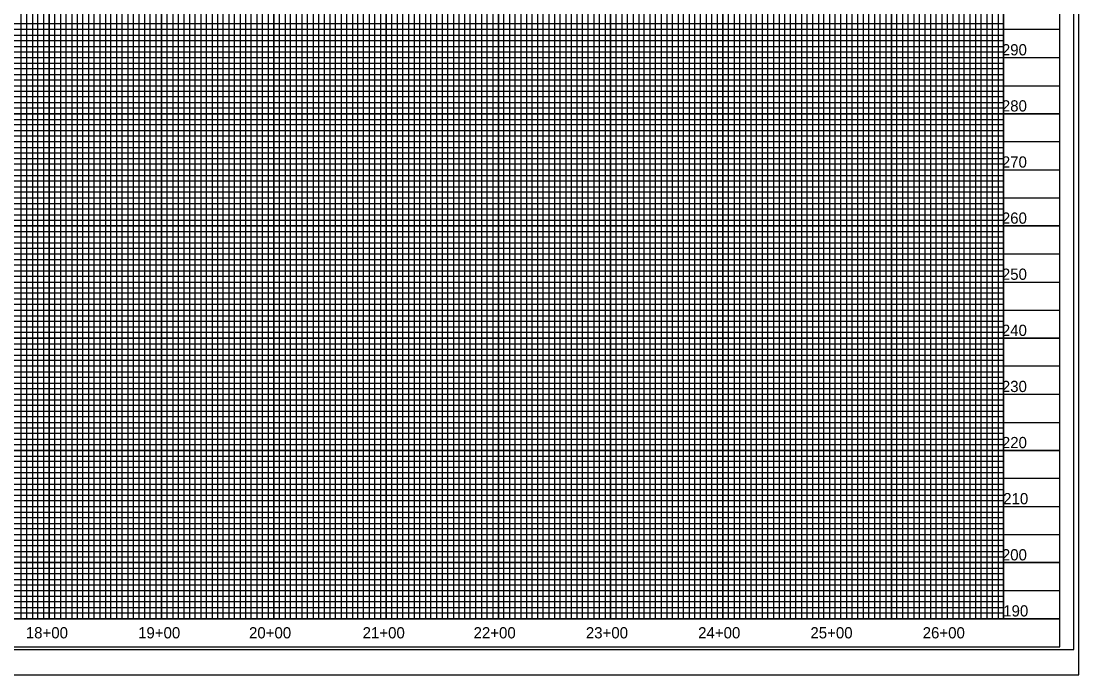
# Model space of a CAD drawing. Extents: x 10033 to 11717, y 9950 to 11050.
# Drawn here: x 10775 to 11717, y 9950 to 10532 of the extents above; entities that cross this region are included whole.
import ezdxf

# ---------------------------------------------------------------- set-up
doc = ezdxf.new("R2010")
doc.units = 0
for name, color, linetype in [('Exist Vertical Profile Horizontal Axis Label Major', 7, 'Continuous'), ('Exist Vertical Profile Vertical Axis Label', 7, 'Continuous'), ('Sheet Cutting Line CELL', 7, 'Continuous'), ('Sheet DOT Grid CELL', 7, 'Continuous'), ('Sheet Layout Profile Border', 7, 'Continuous'), ('Sheet Plot Border Inside CELL', 7, 'Continuous'), ('Sheet Plot Border Outside CELL', 7, 'Continuous'), ('Sheet Profile CELL', 7, 'Continuous'), ('Sheet Profile Grid Major CELL', 7, 'Continuous'), ('Sheet Profile Grid Middle CELL', 7, 'Continuous'), ('Sheet Profile Grid Minor CELL', 7, 'Continuous')]:
    doc.layers.add(name, color=color, linetype=linetype)

msp = doc.modelspace()

# ---------------------------------------------------------------- linework, layer by layer
at = {"layer": 'Sheet Cutting Line CELL'}
msp.add_line((10033, 9950), (11717, 9950), dxfattribs=at)
at = {"layer": 'Sheet DOT Grid CELL'}
for p, q in [((10800, 11025), (10800, 10000)), ((10850, 11025), (10850, 10000)), ((10900, 11025), (10900, 10000)), ((10950, 11025), (10950, 10000)), ((11000, 11025), (11000, 10000)), ((11050, 11025), (11050, 10000)), ((11100, 11025), (11100, 10000)), ((11150, 11025), (11150, 10000)), ((11200, 11025), (11200, 10000)), ((11250, 11025), (11250, 10000)), ((11300, 11025), (11300, 10000)), ((11350, 11025), (11350, 10000)), ((11400, 11025), (11400, 10000)), ((11450, 11025), (11450, 10000)), ((11500, 10000), (11500, 10887.45)), ((11550, 10000), (11550, 10887.45)), ((11600, 10000), (11600, 10887.45)), ((11650, 10000), (11650, 10887.45)), ((10200, 10500), (11700, 10500)), ((10200, 10450), (11700, 10450)), ((10200, 10400), (11700, 10400)), ((10200, 10350), (11700, 10350)), ((10200, 10300), (11700, 10300)), ((10200, 10250), (11700, 10250)), ((10200, 10200), (11700, 10200)), ((10200, 10150), (11700, 10150)), ((10200, 10100), (11700, 10100)), ((10200, 10050), (11700, 10050))]:
    msp.add_line(p, q, dxfattribs=at)
at = {"layer": 'Sheet Layout Profile Border'}
msp.add_lwpolyline([(10250, 11025), (10250, 10000), (11650, 10000), (11650, 10887.45), (11499.95, 10887.45), (11499.95, 11025)], close=True, dxfattribs=at)
at = {"layer": 'Sheet Plot Border Inside CELL'}
msp.add_lwpolyline([(11712.5, 11027.55), (10046, 11027.55), (10046, 9972.45), (11712.5, 9972.45)], close=True, dxfattribs=at)
at = {"layer": 'Sheet Plot Border Outside CELL'}
msp.add_lwpolyline([(11717, 11050), (10033, 11050), (10033, 9950), (11717, 9950)], close=True, dxfattribs=at)
at = {"layer": 'Sheet Profile CELL'}
msp.add_line((11700, 10000), (10200, 10000), dxfattribs=at)
msp.add_lwpolyline([(11700, 11025), (10200, 11025), (10200, 9975), (11700, 9975)], close=True, dxfattribs=at)
at = {"layer": 'Sheet Profile Grid Major CELL'}
for points in [[(10750, 10000), (10800, 10000), (10800, 11025)], [(10850, 11025), (10850, 10000), (10900, 10000), (10900, 11025)], [(10950, 11025), (10950, 10000), (11000, 10000), (11000, 11025)], [(11050, 11025), (11050, 10000), (11100, 10000), (11100, 11025)], [(11150, 11025), (11150, 10000), (11200, 10000), (11200, 11025)], [(11250, 11025), (11250, 10000), (11300, 10000), (11300, 11025)], [(11350, 11025), (11350, 10000), (11400, 10000), (11400, 11025)], [(11450, 11025), (11450, 10000), (11500, 10000), (11500, 11025)], [(11550, 10887.45), (11550, 10000), (11600, 10000), (11600, 10887.45)], [(11650, 10887.45), (11650, 10000), (11700, 10000)], [(11700, 10450), (10200, 10450), (10200, 10500), (11700, 10500)], [(11700, 10350), (10200, 10350), (10200, 10400), (11700, 10400)], [(11700, 10250), (10200, 10250), (10200, 10300), (11700, 10300)], [(11700, 10150), (10200, 10150), (10200, 10200), (11700, 10200)], [(11700, 10050), (10200, 10050), (10200, 10100), (11700, 10100)]]:
    msp.add_lwpolyline(points, dxfattribs=at)
at = {"layer": 'Sheet Profile Grid Middle CELL'}
for points in [[(10725, 10000), (10775, 10000), (10775, 11025)], [(10825, 11025), (10825, 10000), (10875, 10000), (10875, 11025)], [(10925, 11025), (10925, 10000), (10975, 10000), (10975, 11025)], [(11025, 11025), (11025, 10000), (11075, 10000), (11075, 11025)], [(11125, 11025), (11125, 10000), (11175, 10000), (11175, 11025)], [(11225, 11025), (11225, 10000), (11275, 10000), (11275, 11025)], [(11325, 11025), (11325, 10000), (11375, 10000), (11375, 11025)], [(11425, 11025), (11425, 10000), (11475, 10000), (11475, 11025)], [(11525, 10887.45), (11525, 10000), (11575, 10000), (11575, 10887.45)], [(11625, 10887.45), (11625, 10000)], [(11700, 10525), (10200, 10525), (10200, 10475), (11700, 10475)], [(11700, 10425), (10200, 10425), (10200, 10375), (11700, 10375)], [(11700, 10325), (10200, 10325), (10200, 10275), (11700, 10275)], [(11700, 10225), (10200, 10225), (10200, 10175), (11700, 10175)], [(11700, 10125), (10200, 10125), (10200, 10075), (11700, 10075)], [(11700, 10025), (10200, 10025)]]:
    msp.add_lwpolyline(points, dxfattribs=at)
at = {"layer": 'Sheet Profile Grid Minor CELL'}
for points in [[(10780, 10000), (10780, 11025)], [(10785, 11025), (10785, 10000), (10790, 10000), (10790, 11025)], [(10795, 11025), (10795, 10000), (10805, 10000), (10805, 11025)], [(10810, 11025), (10810, 10000), (10810, 10000), (10815, 10000), (10815, 11025)], [(10820, 11025), (10820, 10000), (10830, 10000), (10830, 11025)], [(10835, 11025), (10835, 10000), (10840, 10000), (10840, 11025)], [(10845, 11025), (10845, 10000), (10855, 10000), (10855, 11025)], [(10860, 11025), (10860, 10000), (10865, 10000), (10865, 11025)], [(10870, 11025), (10870, 10000), (10880, 10000), (10880, 11025)], [(10885, 11025), (10885, 10000), (10890, 10000), (10890, 11025)], [(10895, 11025), (10895, 10000), (10905, 10000), (10905, 11025)], [(10910, 11025), (10910, 10000), (10915, 10000), (10915, 11025)], [(10920, 11025), (10920, 10000), (10930, 10000), (10930, 11025)], [(10935, 11025), (10935, 10000), (10940, 10000), (10940, 11025)], [(10945, 11025), (10945, 10000), (10955, 10000), (10955, 11025)], [(10960, 11025), (10960, 10000)], [(10960, 10000), (10965, 10000), (10965, 11024.4)], [(10970, 11024.4), (10970, 10000), (10980, 10000), (10980, 11025)], [(10985, 11025), (10985, 10000), (10990, 10000), (10990, 11025)], [(10995, 11025), (10995, 10000), (11005, 10000), (11005, 11025)], [(11010, 11025), (11010, 10000), (11015, 10000), (11015, 11025)], [(11020, 11025), (11020, 10000), (11030, 10000), (11030, 11025)], [(11035, 11025), (11035, 10000), (11040, 10000), (11040, 11025)], [(11045, 11025), (11045, 10000), (11055, 10000), (11055, 11025)], [(11060, 11025), (11060, 10000), (11065, 10000), (11065, 11025)], [(11070, 11025), (11070, 10000), (11080, 10000), (11080, 11025)], [(11085, 11025), (11085, 10000), (11090, 10000), (11090, 11025)], [(11095, 11025), (11095, 10000), (11105, 10000), (11105, 11025)], [(11110, 11025), (11110, 10000), (11115, 10000), (11115, 11025)], [(11120, 11025), (11120, 10000), (11130, 10000), (11130, 11025)], [(11135, 11025), (11135, 10000), (11140, 10000), (11140, 11025)], [(11145, 11025), (11145, 10000), (11155, 10000), (11155, 11025)], [(11160, 11025), (11160, 10000), (11165, 10000), (11165, 11025)], [(11170, 11025), (11170, 10000), (11180, 10000), (11180, 11025)], [(11185, 11025), (11185, 10000), (11190, 10000), (11190, 11025)], [(11195, 11025), (11195, 10000), (11205, 10000), (11205, 11025)], [(11210, 11025), (11210, 10000), (11215, 10000), (11215, 11025)], [(11220, 11025), (11220, 10000), (11230, 10000), (11230, 11025)], [(11235, 11025), (11235, 10000), (11240, 10000), (11240, 11025)], [(11245, 11025), (11245, 10000), (11255, 10000), (11255, 11025)], [(11260, 11025), (11260, 10000), (11265, 10000), (11265, 11025)], [(11270, 11025), (11270, 10000)], [(11270, 10000), (11280, 10000), (11280, 11025)], [(11285, 11025), (11285, 10000), (11290, 10000), (11290, 11025)], [(11295, 11025), (11295, 10000), (11305, 10000), (11305, 11025)], [(11310, 11025), (11310, 10000), (11315, 10000), (11315, 11025)], [(11320, 11025), (11320, 10000), (11330, 10000), (11330, 11025)], [(11335, 11025), (11335, 10000), (11340, 10000), (11340, 11025)], [(11345, 11025), (11345, 10000), (11355, 10000), (11355, 11025)], [(11360, 11025), (11360, 10000), (11365, 10000), (11365, 11025)], [(11370, 11025), (11370, 10000), (11380, 10000), (11380, 11025)], [(11385, 11025), (11385, 10000), (11390, 10000), (11390, 11025)], [(11395, 11025), (11395, 10000), (11405, 10000), (11405, 11025)], [(11410, 11025), (11410, 10000), (11415, 10000), (11415, 11025)], [(11420, 11025), (11420, 10000), (11430, 10000), (11430, 11025)], [(11435, 11025), (11435, 10000), (11440, 10000), (11440, 11025)], [(11445, 11025), (11445, 10000), (11455, 10000), (11455, 11025)], [(11460, 11025), (11460, 10000), (11465, 10000), (11465, 11025)], [(11470, 11025), (11470, 10000), (11480, 10000), (11480, 11025)], [(11485, 11025), (11485, 10000), (11490, 10000), (11490, 11025)], [(11495, 11025), (11495, 10000), (11505, 10000), (11505, 10887.45)], [(11510, 10887.45), (11510, 10000), (11515, 10000), (11515, 10887.45)], [(11520, 10887.45), (11520, 10000), (11530, 10000), (11530, 10887.45)], [(11535, 10887.45), (11535, 10000), (11540, 10000), (11540, 10887.45)], [(11545, 10887.45), (11545, 10000), (11555, 10000), (11555, 10887.45)], [(11560, 10887.45), (11560, 10000), (11565, 10000), (11565, 10887.45)], [(11570, 10887.45), (11570, 10000), (11580, 10000), (11580, 10887.45)], [(11585, 10887.45), (11585, 10000)], [(11585, 10000), (11590, 10000), (11590, 10887.45)], [(11595, 10887.45), (11595, 10000), (11605, 10000), (11605, 10887.45)], [(11610, 10887.45), (11610, 10000), (11615, 10000), (11615, 10887.45)], [(11620, 10887.45), (11620, 10000), (11630, 10000), (11630, 10887.45)], [(11635, 10887.45), (11635, 10000), (11640, 10000), (11640, 10887.45)], [(11645, 10887.45), (11645, 10000), (11655, 10000)], [(11650, 10530), (10250, 10530), (10250, 10520), (11650, 10520)], [(11650, 10515), (10250, 10515), (10250, 10510), (11650, 10510)], [(11650, 10505), (10250, 10505)], [(10250, 10495), (11650, 10495)], [(11650, 10490), (10250, 10490), (10250, 10485), (11650, 10485)], [(11650, 10480), (10250, 10480), (10250, 10470), (11650, 10470)], [(11650, 10465), (10250, 10465), (10250, 10460), (11650, 10460)], [(11650, 10455), (10250, 10455), (10250, 10445), (11650, 10445)], [(11650, 10440), (10250, 10440), (10250, 10435), (11650, 10435)], [(11650, 10430), (10250, 10430), (10250, 10420), (11650, 10420)], [(11650, 10415), (10250, 10415), (10250, 10410), (11650, 10410)], [(11650, 10405), (10250, 10405), (10250, 10395), (11650, 10395)], [(11650, 10390), (10250, 10390), (10250, 10385), (11650, 10385)], [(11650, 10380), (10250, 10380), (10250, 10370), (11650, 10370)], [(11650, 10365), (10250, 10365), (10250, 10360), (11650, 10360)], [(11650, 10355), (10250, 10355), (10250, 10345), (11650, 10345)], [(11650, 10340), (10250, 10340), (10250, 10335), (11650, 10335)], [(11650, 10330), (10250, 10330), (10250, 10320), (11650, 10320)], [(11650, 10315), (10250, 10315), (10250, 10310), (11650, 10310)], [(11650, 10305), (10250, 10305), (10250, 10295), (11650, 10295)], [(11650, 10290), (10250, 10290), (10250, 10285), (11650, 10285)], [(11650, 10280), (10250, 10280), (10250, 10270), (11650, 10270)], [(11650, 10265), (10250, 10265), (10250, 10260), (11650, 10260)], [(11650, 10255), (10250, 10255), (10250, 10245), (11650, 10245)], [(11650, 10240), (10250, 10240), (10250, 10235), (11650, 10235)], [(11650, 10230), (10250, 10230), (10250, 10220), (11650, 10220)], [(11650, 10215), (10250, 10215), (10250, 10210), (11650, 10210)], [(11650, 10205), (10250, 10205)], [(10250, 10195), (11650, 10195)], [(11650, 10190), (10250, 10190), (10250, 10185), (11650, 10185)], [(11650, 10180), (10250, 10180)], [(10250, 10170), (11650, 10170)], [(11650, 10165), (10250, 10165), (10250, 10160), (11650, 10160)], [(11650, 10155), (10250, 10155), (10250, 10145), (11650, 10145)], [(11650, 10140), (10250, 10140), (10250, 10135), (11650, 10135)], [(11650, 10130), (10250, 10130), (10250, 10120), (11650, 10120)], [(11650, 10115), (10250, 10115), (10250, 10110), (11650, 10110)], [(11650, 10105), (10250, 10105), (10250, 10095), (11650, 10095)], [(11650, 10090), (10250, 10090), (10250, 10085), (11650, 10085)], [(11650, 10080), (10250, 10080), (10250, 10070), (11650, 10070)], [(11650, 10065), (10250, 10065), (10250, 10060), (11650, 10060)], [(11650, 10055), (10250, 10055), (10250, 10045), (11650, 10045)], [(11650, 10040), (10250, 10040), (10250, 10035), (11650, 10035)], [(11650, 10030), (10250, 10030), (10250, 10020), (11650, 10020)], [(11650, 10015), (10250, 10015), (10250, 10010), (11650, 10010)], [(11650, 10005), (10250, 10005)]]:
    msp.add_lwpolyline(points, dxfattribs=at)

# ---------------------------------------------------------------- texts
at = {"layer": 'Exist Vertical Profile Horizontal Axis Label Major'}
for s, p in [('18+00', (10779.13, 9982.5)), ('19+00', (10879.13, 9982.5)), ('20+00', (10977.93, 9982.5)), ('21+00', (11079.13, 9982.5)), ('22+00', (11177.93, 9982.5)), ('23+00', (11277.93, 9982.5)), ('24+00', (11377.93, 9982.5)), ('25+00', (11477.93, 9982.5)), ('26+00', (11577.93, 9982.5))]:
    msp.add_text(s, height=10, dxfattribs=at).set_placement(p)
at = {"layer": 'Exist Vertical Profile Vertical Axis Label'}
for s, p in [('290', (11648.43, 10502)), ('280', (11648.43, 10452)), ('270', (11648.43, 10402)), ('260', (11648.43, 10352)), ('250', (11648.43, 10302)), ('240', (11648.43, 10252)), ('230', (11648.43, 10202)), ('220', (11648.43, 10152)), ('210', (11649.63, 10102)), ('200', (11648.43, 10052)), ('190', (11649.63, 10002))]:
    msp.add_text(s, height=10, dxfattribs=at).set_placement(p)

doc.saveas('drawing.dxf')
